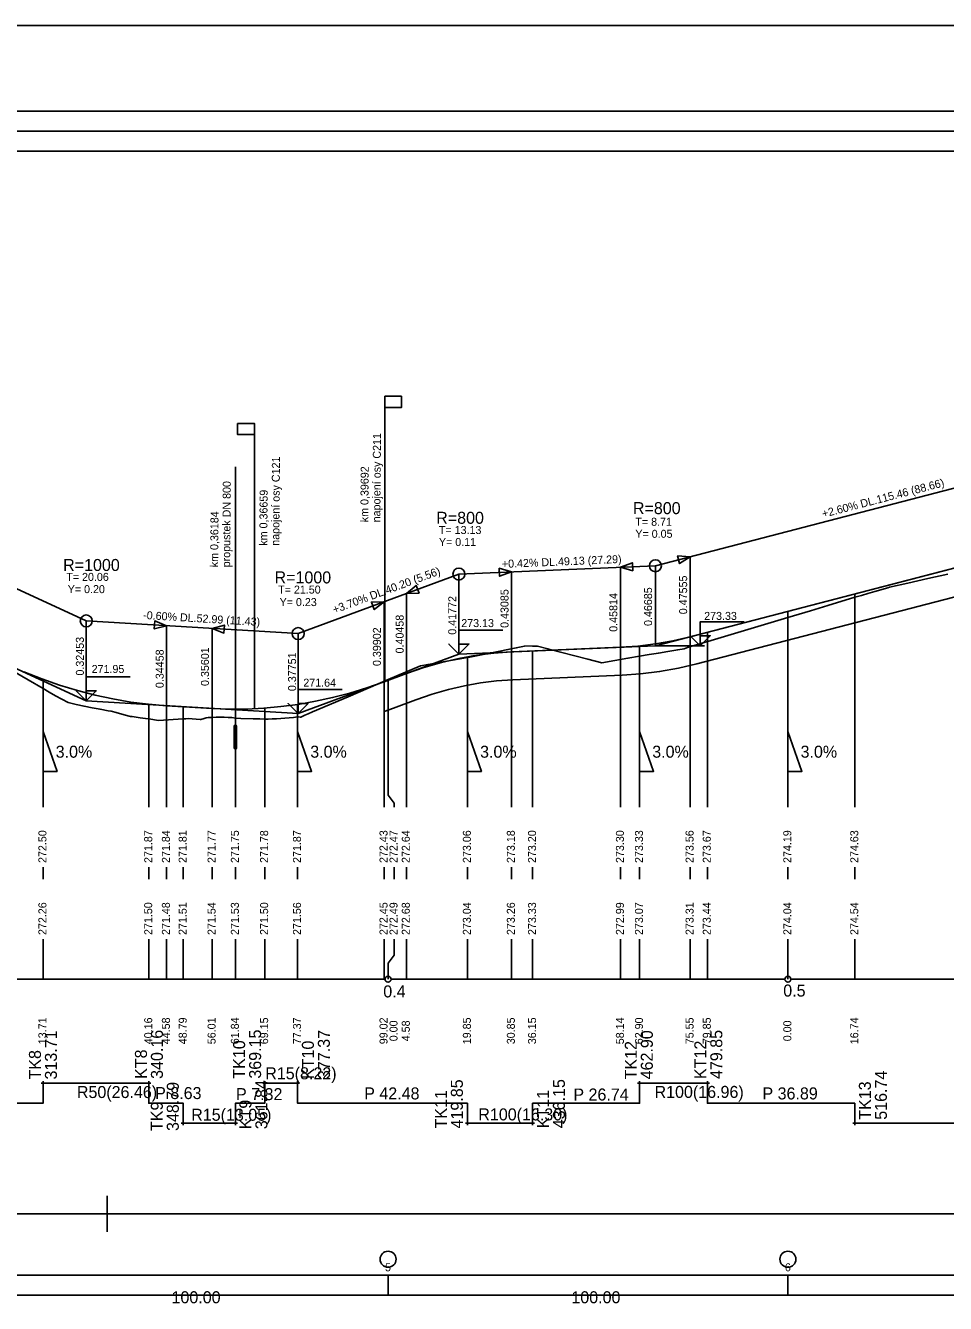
# Model space of a CAD drawing. Extents: x 1531 to 1699, y 61 to 93.
# Drawn here: x 1570.63 to 1593.63, y 60.9 to 92.84 of the extents above; entities that cross this region are included whole.
import ezdxf

# ---------------------------------------------------------------- set-up
doc = ezdxf.new("R2010")
doc.units = 0
for name, color, linetype in [('KOTA', 7, 'Continuous'), ('NOVY_STAV', 7, 'Continuous'), ('NS_OBLOUK', 7, 'Continuous'), ('Propustek', 7, 'Continuous'), ('REZY_PO', 7, 'Continuous'), ('SESTAVY_REZU_PO', 7, 'Continuous'), ('SKLONOVE_POMERY', 7, 'Continuous'), ('SMEROVE_POMERY', 7, 'Continuous'), ('SMEROVE_POMERY_KOD', 7, 'Continuous'), ('SVK_STAT', 7, 'Continuous'), ('TABULKY', 7, 'Continuous'), ('u_drenaz', 7, 'Continuous'), ('u_pricne_rezy', 7, 'Continuous'), ('x_formát_rám', 7, 'Continuous')]:
    doc.layers.add(name, color=color, linetype=linetype)

msp = doc.modelspace()

# ---------------------------------------------------------------- linework, layer by layer
at = {"layer": 'KOTA'}
msp.add_line((1586.379, 77.333), (1587.605, 77.333), dxfattribs=at)
for points in [[(1587.502, 77.333), (1587.252, 77.583), (1587.502, 77.333), (1587.502, 77.933), (1588.602, 77.933)], [(1581.466, 77.127), (1581.216, 77.377), (1581.466, 77.127), (1581.466, 77.727), (1582.566, 77.727)], [(1581.466, 77.377), (1581.466, 77.127), (1581.716, 77.377), (1581.466, 77.377)], [(1581.466, 77.127), (1581.716, 77.377), (1581.466, 77.377)], [(1587.502, 77.583), (1587.502, 77.333), (1587.752, 77.583), (1587.502, 77.583)], [(1587.502, 77.333), (1587.752, 77.583), (1587.502, 77.583)], [(1587.502, 77.333), (1587.502, 77.333)], [(1581.466, 77.127), (1581.466, 77.127)], [(1572.147, 75.955), (1571.897, 76.205), (1572.147, 75.955), (1572.147, 76.555), (1573.247, 76.555)], [(1572.147, 76.205), (1572.147, 75.955), (1572.397, 76.205), (1572.147, 76.205)], [(1572.147, 75.955), (1572.397, 76.205), (1572.147, 76.205)], [(1577.446, 75.638), (1577.196, 75.888), (1577.446, 75.638), (1577.446, 76.238), (1578.546, 76.238)], [(1572.147, 75.955), (1572.147, 75.955)], [(1577.446, 75.888), (1577.446, 75.638), (1577.696, 75.888), (1577.446, 75.888)], [(1577.446, 75.638), (1577.696, 75.888), (1577.446, 75.888)]]:
    msp.add_lwpolyline(points, dxfattribs=at)
at = {"layer": 'NOVY_STAV'}
for p, q in [((1579.614, 76.442), (1579.614, 83.29)), ((1576.353, 75.762), (1576.353, 82.611)), ((1575.878, 74.751), (1575.878, 81.807))]:
    msp.add_line(p, q, dxfattribs=at)
for points in [[(1539.694, 84.06), (1549.705, 82.699), (1562.624, 80.344), (1572.147, 75.955), (1577.446, 75.638), (1581.466, 77.127), (1586.379, 77.333), (1597.924, 80.331), (1615.27, 83.267), (1630.35, 84.047), (1639.808, 81.89), (1648.745, 76.875), (1657.192, 78.43), (1660.774, 78.567), (1665.184, 79.201), (1673.611, 79.536), (1676.863, 81.654)], [(1562.624, 82.344), (1572.147, 77.955)], [(1586.379, 79.333), (1597.924, 82.331)], [(1570.587, 76.684), (1571.033, 76.508), (1571.478, 76.352), (1571.924, 76.217), (1572.37, 76.101), (1572.815, 76.004), (1573.261, 75.928), (1573.707, 75.872), (1574.152, 75.835), (1575.295, 75.767), (1575.725, 75.75), (1576.155, 75.752), (1576.585, 75.773), (1577.015, 75.812), (1577.446, 75.87), (1577.876, 75.946), (1578.306, 76.04), (1578.736, 76.153), (1579.166, 76.285), (1579.596, 76.435), (1580.152, 76.641), (1580.59, 76.791), (1581.028, 76.917), (1581.466, 77.019), (1581.904, 77.098), (1582.341, 77.152), (1582.779, 77.182), (1585.508, 77.297), (1585.943, 77.327), (1586.379, 77.381), (1586.814, 77.458), (1587.25, 77.56), (1596.116, 79.862)], [(1581.466, 79.127), (1586.379, 79.333)], [(1586.379, 77.333), (1586.379, 79.333)], [(1577.446, 77.638), (1581.466, 79.127)], [(1581.466, 77.127), (1581.466, 79.127)], [(1572.147, 75.955), (1572.147, 77.955)], [(1572.147, 77.955), (1577.446, 77.638)], [(1577.446, 75.638), (1577.446, 77.638)]]:
    msp.add_lwpolyline(points, dxfattribs=at)
for points in [[(1580.034, 83.57), (1579.614, 83.57), (1579.614, 83.29), (1580.034, 83.29)], [(1575.933, 82.891), (1576.353, 82.891), (1576.353, 82.611), (1575.933, 82.611)]]:
    msp.add_lwpolyline(points, close=True, dxfattribs=at)
for centre in [(1581.466, 79.127), (1586.379, 79.333), (1572.147, 77.955), (1577.446, 77.638)]:
    msp.add_circle(centre, 0.15, dxfattribs=at)
at = {"layer": 'NS_OBLOUK'}
for points in [[(1586.984, 79.387), (1587.25, 79.56), (1586.934, 79.581), (1586.984, 79.387)], [(1587.25, 77.56), (1587.25, 79.56)], [(1582.484, 79.07), (1582.779, 79.182), (1582.475, 79.27), (1582.484, 79.07)], [(1585.508, 79.297), (1585.812, 79.21), (1585.804, 79.409), (1585.508, 79.297)], [(1585.508, 77.297), (1585.508, 79.297)], [(1582.779, 77.182), (1582.779, 79.182)], [(1580.152, 78.641), (1580.469, 78.651), (1580.399, 78.839), (1580.152, 78.641)], [(1580.152, 76.641), (1580.152, 78.641)], [(1579.349, 78.237), (1579.596, 78.435), (1579.28, 78.424), (1579.349, 78.237)], [(1579.596, 76.435), (1579.596, 78.435)], [(1573.847, 77.753), (1574.153, 77.835), (1573.859, 77.953), (1573.847, 77.753)], [(1574.153, 75.835), (1574.153, 77.835)], [(1575.295, 77.767), (1575.589, 77.649), (1575.601, 77.849), (1575.295, 77.767)], [(1575.295, 75.767), (1575.295, 77.767)]]:
    msp.add_lwpolyline(points, dxfattribs=at)
for points in [[(1587.25, 79.56), (1586.934, 79.581), (1586.984, 79.387)], [(1582.779, 79.182), (1582.475, 79.27), (1582.484, 79.07)], [(1585.508, 79.297), (1585.804, 79.409), (1585.812, 79.21)], [(1580.152, 78.641), (1580.399, 78.839), (1580.469, 78.651)], [(1579.596, 78.435), (1579.28, 78.424), (1579.349, 78.237)], [(1574.153, 77.835), (1573.859, 77.953), (1573.847, 77.753)], [(1575.295, 77.767), (1575.601, 77.849), (1575.589, 77.649)]]:
    msp.add_lwpolyline(points, close=True, dxfattribs=at)
at = {"layer": 'Propustek'}
for p, q in [((1575.848, 74.781), (1575.848, 75.321)), ((1575.908, 74.781), (1575.908, 75.321))]:
    msp.add_line(p, q, dxfattribs=at)
for centre, start, end in [((1575.878, 75.321), 0.0004, 179.9996), ((1575.878, 74.781), 179.9996, 0.0004)]:
    msp.add_arc(centre, 0.03, start, end, dxfattribs=at)
at = {"layer": 'REZY_PO'}
msp.add_lwpolyline([(1569.694, 77.058), (1570.694, 76.479), (1571.065, 76.264), (1571.065, 76.264), (1571.065, 76.264), (1571.222, 76.174), (1571.38, 76.085), (1571.537, 75.997), (1571.693, 75.912), (1571.694, 75.912), (1571.894, 75.867), (1572.094, 75.824), (1572.294, 75.784), (1572.494, 75.746), (1572.694, 75.71), (1572.767, 75.698), (1572.894, 75.664), (1573.094, 75.61), (1573.25, 75.567), (1573.294, 75.562), (1573.494, 75.535), (1573.694, 75.507), (1573.702, 75.506), (1573.711, 75.505), (1573.952, 75.47), (1574.573, 75.508), (1574.634, 75.511), (1574.694, 75.512), (1574.794, 75.51), (1574.894, 75.503), (1574.994, 75.492), (1575.011, 75.489), (1575.094, 75.517), (1575.142, 75.531), (1575.194, 75.537), (1575.294, 75.544), (1575.394, 75.548), (1575.494, 75.55), (1575.594, 75.548), (1575.694, 75.544), (1575.786, 75.537), (1575.878, 75.528), (1575.878, 75.528), (1575.878, 75.528), (1576.01, 75.513), (1576.32, 75.507), (1576.49, 75.504), (1576.609, 75.503), (1576.609, 75.503), (1576.609, 75.503), (1576.652, 75.503), (1576.694, 75.503), (1576.8, 75.504), (1576.905, 75.508), (1577.01, 75.514), (1577.116, 75.521), (1577.221, 75.531), (1577.326, 75.543), (1577.432, 75.556), (1577.449, 75.559), (1577.5, 75.55), (1577.512, 75.551), (1577.617, 75.6), (1577.694, 75.633), (1577.806, 75.681), (1578.694, 76.061), (1579.694, 76.488), (1579.694, 76.488), (1580.503, 76.833), (1580.694, 76.867), (1581.679, 77.042), (1581.679, 77.042), (1581.679, 77.042), (1581.687, 77.043), (1581.694, 77.044), (1581.944, 77.09), (1582.194, 77.137), (1582.444, 77.187), (1582.694, 77.239), (1582.899, 77.282), (1583.104, 77.327), (1583.116, 77.33), (1583.31, 77.327), (1583.431, 77.325), (1583.694, 77.257), (1583.712, 77.253), (1584.694, 76.999), (1585.044, 76.909), (1585.694, 77.021), (1585.984, 77.071), (1586.221, 77.112), (1586.457, 77.153), (1586.694, 77.193), (1586.941, 77.235), (1587.098, 77.261), (1587.187, 77.288), (1587.433, 77.363), (1587.68, 77.437), (1587.694, 77.441), (1588.694, 77.742), (1589.694, 78.042), (1589.694, 78.042), (1590.257, 78.211), (1590.694, 78.342), (1591.368, 78.545), (1591.531, 78.594), (1591.694, 78.643), (1591.866, 78.694), (1592.194, 78.786), (1592.234, 78.797), (1592.694, 78.9), (1593.194, 79.013), (1593.694, 79.126)], dxfattribs=at)
at = {"layer": 'SESTAVY_REZU_PO'}
for points in [[(1569.769, 69), (1579.619, 69)], [(1579.769, 69), (1589.619, 69)], [(1589.769, 69), (1599.619, 69)]]:
    msp.add_lwpolyline(points, dxfattribs=at)
for centre in [(1579.694, 69), (1589.694, 69)]:
    msp.add_circle(centre, 0.075, dxfattribs=at)
at = {"layer": 'SKLONOVE_POMERY'}
for points in [[(1571.065, 74.192), (1571.065, 75.192), (1571.065, 75.192), (1571.24, 74.692), (1571.415, 74.192), (1571.065, 74.192)], [(1577.432, 74.192), (1577.432, 75.192), (1577.432, 75.192), (1577.607, 74.692), (1577.782, 74.192), (1577.432, 74.192)], [(1581.679, 74.192), (1581.679, 75.192), (1581.679, 75.192), (1581.854, 74.692), (1582.029, 74.192), (1581.679, 74.192)], [(1585.984, 74.192), (1585.984, 75.192), (1585.984, 75.192), (1586.159, 74.692), (1586.334, 74.192), (1585.984, 74.192)], [(1589.694, 74.192), (1589.694, 75.192), (1589.694, 75.192), (1589.869, 74.692), (1590.044, 74.192), (1589.694, 74.192)]]:
    msp.add_lwpolyline(points, dxfattribs=at)
at = {"layer": 'SMEROVE_POMERY'}
msp.add_lwpolyline([(1568.114, 65.899), (1571.065, 65.899), (1571.065, 66.399), (1573.711, 66.399), (1573.711, 65.899), (1574.573, 65.899), (1574.573, 65.399), (1575.878, 65.399), (1575.878, 65.899), (1576.609, 65.899), (1576.609, 66.399), (1577.432, 66.399), (1577.432, 65.899), (1581.679, 65.899), (1581.679, 65.399), (1583.31, 65.399), (1583.31, 65.899), (1585.984, 65.899), (1585.984, 66.399), (1587.68, 66.399), (1587.68, 65.899), (1591.368, 65.899), (1591.368, 65.399), (1604.901, 65.399)], dxfattribs=at)
at = {"layer": 'SMEROVE_POMERY_KOD'}
for points in [[(1571.065, 66.349), (1571.065, 66.449)], [(1573.711, 66.349), (1573.711, 66.449)], [(1576.609, 66.349), (1576.609, 66.449)], [(1577.432, 66.349), (1577.432, 66.449)], [(1585.984, 66.349), (1585.984, 66.449)], [(1587.68, 66.349), (1587.68, 66.449)], [(1571.015, 66.399), (1571.115, 66.399)], [(1573.661, 66.399), (1573.761, 66.399)], [(1576.559, 66.399), (1576.659, 66.399)], [(1577.382, 66.399), (1577.482, 66.399)], [(1585.934, 66.399), (1586.034, 66.399)], [(1587.63, 66.399), (1587.73, 66.399)], [(1574.523, 65.399), (1574.623, 65.399)], [(1574.573, 65.349), (1574.573, 65.449)], [(1575.828, 65.399), (1575.928, 65.399)], [(1575.878, 65.349), (1575.878, 65.449)], [(1581.629, 65.399), (1581.729, 65.399)], [(1581.679, 65.349), (1581.679, 65.449)], [(1583.26, 65.399), (1583.36, 65.399)], [(1583.31, 65.349), (1583.31, 65.449)], [(1591.318, 65.399), (1591.418, 65.399)], [(1591.368, 65.349), (1591.368, 65.449)]]:
    msp.add_lwpolyline(points, dxfattribs=at)
at = {"layer": 'SVK_STAT'}
for points in [[(1591.368, 73.3), (1591.368, 78.629)], [(1589.694, 73.3), (1589.694, 78.194)], [(1587.68, 73.3), (1587.68, 77.671)], [(1585.508, 73.3), (1585.508, 77.297)], [(1585.984, 73.3), (1585.984, 77.332)], [(1587.25, 73.3), (1587.25, 77.56)], [(1581.679, 73.3), (1581.679, 77.058)], [(1582.779, 73.3), (1582.779, 77.182)], [(1583.31, 73.3), (1583.31, 77.205)], [(1571.065, 73.3), (1571.065, 76.497)], [(1579.596, 73.3), (1579.596, 76.435)], [(1579.846, 73.3), (1579.846, 73.4), (1579.694, 73.6), (1579.694, 76.471)], [(1580.152, 73.3), (1580.152, 76.641)], [(1573.711, 73.3), (1573.711, 75.871)], [(1574.153, 73.3), (1574.153, 75.835)], [(1574.573, 73.3), (1574.573, 75.81)], [(1575.295, 73.3), (1575.295, 75.767)], [(1575.878, 73.3), (1575.878, 75.751)], [(1576.609, 73.3), (1576.609, 75.775)], [(1577.432, 73.3), (1577.432, 75.868)], [(1571.065, 71.5), (1571.065, 71.8)], [(1573.711, 71.5), (1573.711, 71.8)], [(1574.153, 71.5), (1574.153, 71.8)], [(1574.573, 71.5), (1574.573, 71.8)], [(1575.295, 71.5), (1575.295, 71.8)], [(1575.878, 71.5), (1575.878, 71.8)], [(1576.609, 71.5), (1576.609, 71.8)], [(1577.432, 71.5), (1577.432, 71.8)], [(1579.596, 71.5), (1579.596, 71.8)], [(1579.846, 71.5), (1579.846, 71.8)], [(1580.152, 71.5), (1580.152, 71.8)], [(1581.679, 71.5), (1581.679, 71.8)], [(1582.779, 71.5), (1582.779, 71.8)], [(1583.31, 71.5), (1583.31, 71.8)], [(1585.508, 71.5), (1585.508, 71.8)], [(1585.984, 71.5), (1585.984, 71.8)], [(1587.25, 71.5), (1587.25, 71.8)], [(1587.68, 71.5), (1587.68, 71.8)], [(1589.694, 71.5), (1589.694, 71.8)], [(1591.368, 71.5), (1591.368, 71.8)], [(1571.065, 69), (1571.065, 70)], [(1573.711, 69), (1573.711, 70)], [(1574.153, 69), (1574.153, 70)], [(1574.573, 69), (1574.573, 70)], [(1575.295, 69), (1575.295, 70)], [(1575.878, 69), (1575.878, 70)], [(1576.609, 69), (1576.609, 70)], [(1577.432, 69), (1577.432, 70)], [(1579.596, 69), (1579.596, 70)], [(1579.694, 69), (1579.694, 69.4), (1579.846, 69.6), (1579.846, 70)], [(1580.152, 69), (1580.152, 70)], [(1581.679, 69), (1581.679, 70)], [(1582.779, 69), (1582.779, 70)], [(1583.31, 69), (1583.31, 70)], [(1585.508, 69), (1585.508, 70)], [(1585.984, 69), (1585.984, 70)], [(1587.25, 69), (1587.25, 70)], [(1587.68, 69), (1587.68, 70)], [(1589.694, 69), (1589.694, 70)], [(1591.368, 69), (1591.368, 70)]]:
    msp.add_lwpolyline(points, dxfattribs=at)
at = {"layer": 'TABULKY'}
for points in [[(1539.694, 89.697), (1676.863, 89.697), (1676.863, 90.697), (1539.694, 90.697), (1539.694, 89.697)], [(1539.694, 90.197), (1676.863, 90.197)]]:
    msp.add_lwpolyline(points, dxfattribs=at)
at = {"layer": 'u_drenaz'}
msp.add_lwpolyline([(1579.596, 75.693), (1579.833, 75.776), (1580.388, 75.981), (1580.801, 76.123), (1581.205, 76.24), (1581.607, 76.334), (1582.008, 76.405), (1582.409, 76.455), (1582.818, 76.483), (1585.547, 76.598), (1586.011, 76.63), (1586.483, 76.688), (1586.955, 76.772), (1587.417, 76.88), (1596.29, 79.184)], dxfattribs=at)
at = {"layer": 'u_pricne_rezy'}
for points in [[(1539.694, 61.1), (1676.863, 61.1), (1676.863, 61.6), (1539.694, 61.6), (1539.694, 61.1)], [(1579.694, 61.1), (1579.694, 61.6)], [(1589.694, 61.1), (1589.694, 61.6)]]:
    msp.add_lwpolyline(points, dxfattribs=at)
for centre in [(1579.694, 62), (1589.694, 62)]:
    msp.add_circle(centre, 0.2, dxfattribs=at)
at = {"layer": 'x_formát_rám'}
msp.add_line((1572.673, 63.586), (1572.673, 62.686), dxfattribs=at)
msp.add_lwpolyline([(1530.673, 63.136), (1698.673, 63.136), (1698.673, 92.836), (1530.673, 92.836)], close=True, dxfattribs=at)

# ---------------------------------------------------------------- texts
at = {"layer": 'KOTA'}
for s, p in [('273.13', (1581.525, 77.801)), ('273.33', (1587.6, 77.98)), ('271.95', (1572.281, 76.653)), ('271.64', (1577.575, 76.311))]:
    msp.add_text(s, height=0.2, dxfattribs=at).set_placement(p)
at = {"layer": 'NOVY_STAV'}
for s, rotation, p in [('napojení osy C211', 89.5404, (1579.5, 80.419)), ('napojení osy C121', 89.5404, (1576.973, 79.832)), ('km 0,39692', 89.5404, (1579.2, 80.421)), ('+2.60% DL.115.46 (88.66)', 14.5564, (1590.577, 80.532)), ('propustek DN 800', 89.5404, (1575.744, 79.294)), ('km 0,36659', 89.5404, (1576.673, 79.835)), ('km 0,36184', 89.5404, (1575.444, 79.296)), ('+0.42% DL.49.13 (27.29)', 2.4037, (1582.545, 79.278)), ('+3.70% DL.40.20 (5.56)', 20.3209, (1578.352, 78.135)), (' 0.46685', 90, (1586.297, 77.754)), (' 0.41772', 90, (1581.4, 77.536)), ('-0.60% DL.52.99 (11.43)', 356.5809, (1573.565, 78.004)), (' 0.32453', 90, (1572.087, 76.515)), (' 0.37751', 90, (1577.394, 76.126))]:
    msp.add_text(s, height=0.2, rotation=rotation, dxfattribs=at).set_placement(p)
at = {"layer": 'NS_OBLOUK'}
for s, height, p in [('R=800', 0.3, (1585.818, 80.624)), ('R=800', 0.3, (1580.899, 80.382)), ('T= 8.71', 0.2, (1585.879, 80.333)), ('T= 13.13', 0.2, (1580.966, 80.127)), ('Y= 0.05', 0.2, (1585.879, 80.033)), ('Y= 0.11', 0.2, (1580.966, 79.827)), ('R=1000', 0.3, (1571.568, 79.203)), ('T= 20.06', 0.2, (1571.647, 78.955)), ('R=1000', 0.3, (1576.855, 78.893)), ('Y= 0.20', 0.2, (1571.683, 78.649)), ('T= 21.50', 0.2, (1576.946, 78.638)), ('Y= 0.23', 0.2, (1576.982, 78.326))]:
    msp.add_text(s, height=height, dxfattribs=at).set_placement(p)
for s, p in [(' 0.47555', (1587.174, 78.047)), (' 0.43085', (1582.707, 77.706)), (' 0.45814', (1585.428, 77.609)), (' 0.40458', (1580.084, 77.068)), (' 0.39902', (1579.515, 76.753)), (' 0.34458', (1574.083, 76.202)), (' 0.35601', (1575.215, 76.254))]:
    msp.add_text(s, height=0.2, rotation=90, dxfattribs=at).set_placement(p)
at = {"layer": 'SESTAVY_REZU_PO'}
for s, p in [('0.4', (1579.575, 68.545)), ('0.5', (1589.578, 68.566))]:
    msp.add_text(s, height=0.3, dxfattribs=at).set_placement(p)
at = {"layer": 'SKLONOVE_POMERY'}
for p in [(1571.382, 74.536), (1577.748, 74.536), (1581.996, 74.536), (1586.301, 74.536), (1590.011, 74.536)]:
    msp.add_text('3.0%', height=0.3, dxfattribs=at).set_placement(p)
at = {"layer": 'SMEROVE_POMERY'}
for s, p in [('R15(8.22)', (1576.623, 66.498)), ('R50(26.46)', (1571.912, 66.03)), ('P 8.63', (1573.869, 66.004)), ('P 7.32', (1575.892, 65.977)), ('P 42.48', (1579.098, 65.995)), ('P 26.74', (1584.329, 65.968)), ('R100(16.96)', (1586.359, 66.033)), ('P 36.89', (1589.058, 65.995)), ('R15(13.05)', (1574.771, 65.462)), ('R100(16.30)', (1581.952, 65.471))]:
    msp.add_text(s, height=0.3, dxfattribs=at).set_placement(p)
at = {"layer": 'SMEROVE_POMERY_KOD'}
for s, p in [('340.16', (1574.064, 66.508)), ('369.15', (1576.519, 66.514)), ('479.85', (1588.054, 66.505)), ('313.71', (1571.413, 66.493)), ('TK10', (1576.119, 66.514)), ('KT10', (1577.839, 66.505)), ('377.37', (1578.239, 66.505)), ('TK12', (1585.916, 66.496)), ('462.90', (1586.316, 66.496)), ('KT12', (1587.654, 66.505)), ('TK8', (1571.013, 66.493)), ('KT8', (1573.664, 66.508)), ('361.84', (1576.676, 65.251)), ('419.85', (1581.565, 65.269)), ('436.15', (1584.117, 65.275)), ('516.74', (1592.169, 65.487)), ('348.79', (1574.461, 65.206)), ('TK11', (1581.165, 65.269)), ('KT11', (1583.717, 65.275)), ('TK13', (1591.769, 65.487)), ('TK9', (1574.061, 65.206)), ('KT9', (1576.276, 65.251))]:
    msp.add_text(s, height=0.3, rotation=90, dxfattribs=at).set_placement(p)
at = {"layer": 'SVK_STAT'}
for s, p in [(' 272.50', (1571.15, 71.83)), (' 271.87', (1573.796, 71.83)), (' 271.84', (1574.238, 71.83)), (' 271.81', (1574.658, 71.83)), (' 271.77', (1575.381, 71.83)), (' 271.75', (1575.963, 71.83)), (' 271.78', (1576.695, 71.83)), (' 271.87', (1577.517, 71.83)), (' 272.43', (1579.681, 71.83)), (' 272.47', (1579.931, 71.83)), (' 272.64', (1580.238, 71.83)), (' 273.06', (1581.765, 71.83)), (' 273.18', (1582.865, 71.83)), (' 273.20', (1583.395, 71.83)), (' 273.30', (1585.593, 71.83)), (' 273.33', (1586.069, 71.83)), (' 273.56', (1587.335, 71.83)), (' 273.67', (1587.765, 71.83)), (' 274.19', (1589.78, 71.83)), (' 274.63', (1591.454, 71.83)), (' 272.26', (1571.15, 70.03)), (' 271.50', (1573.796, 70.03)), (' 271.48', (1574.238, 70.03)), (' 271.51', (1574.658, 70.03)), (' 271.54', (1575.381, 70.03)), (' 271.53', (1575.963, 70.03)), (' 271.50', (1576.695, 70.03)), (' 271.56', (1577.517, 70.03)), (' 272.45', (1579.681, 70.03)), (' 272.49', (1579.931, 70.03)), (' 272.68', (1580.238, 70.03)), (' 273.04', (1581.765, 70.03)), (' 273.26', (1582.865, 70.03)), (' 273.33', (1583.395, 70.03)), (' 272.99', (1585.593, 70.03)), (' 273.07', (1586.069, 70.03)), (' 273.31', (1587.335, 70.03)), (' 273.44', (1587.765, 70.03)), (' 274.04', (1589.78, 70.03)), (' 274.54', (1591.454, 70.03)), (' 40.16', (1573.796, 67.3)), (' 44.58', (1574.238, 67.3)), (' 61.84', (1575.963, 67.3)), (' 69.15', (1576.695, 67.3)), (' 19.85', (1581.765, 67.3)), (' 30.85', (1582.865, 67.3)), (' 36.15', (1583.395, 67.3)), (' 58.14', (1585.593, 67.3)), (' 62.90', (1586.069, 67.3)), (' 75.55', (1587.335, 67.3)), (' 79.85', (1587.765, 67.3)), (' 16.74', (1591.454, 67.3)), (' 13.71', (1571.15, 67.3)), (' 48.79', (1574.658, 67.3)), (' 56.01', (1575.381, 67.3)), (' 77.37', (1577.517, 67.3)), (' 99.02', (1579.681, 67.3)), ('  0.00', (1579.931, 67.3)), ('  4.58', (1580.238, 67.3)), ('  0.00', (1589.78, 67.3))]:
    msp.add_text(s, height=0.2, rotation=90, dxfattribs=at).set_placement(p)
at = {"layer": 'u_pricne_rezy'}
for s, height, p in [('5', 0.2, (1579.619, 61.7)), ('6', 0.2, (1589.619, 61.7)), ('100.00', 0.3, (1574.279, 60.9)), ('100.00', 0.3, (1584.279, 60.9))]:
    msp.add_text(s, height=height, dxfattribs=at).set_placement(p)

doc.saveas('drawing.dxf')
